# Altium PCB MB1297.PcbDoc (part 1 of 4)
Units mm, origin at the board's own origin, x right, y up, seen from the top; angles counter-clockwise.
Board outline 90.1 x 62.11 mm, 4 copper layers (Top Layer, GND, POWER+GND, Bottom Layer), stack 0.778 mm thick; 235 components, 175 nets, 1727 pads, 1 vias.
Unrouted connection lines stored in the file: 1.
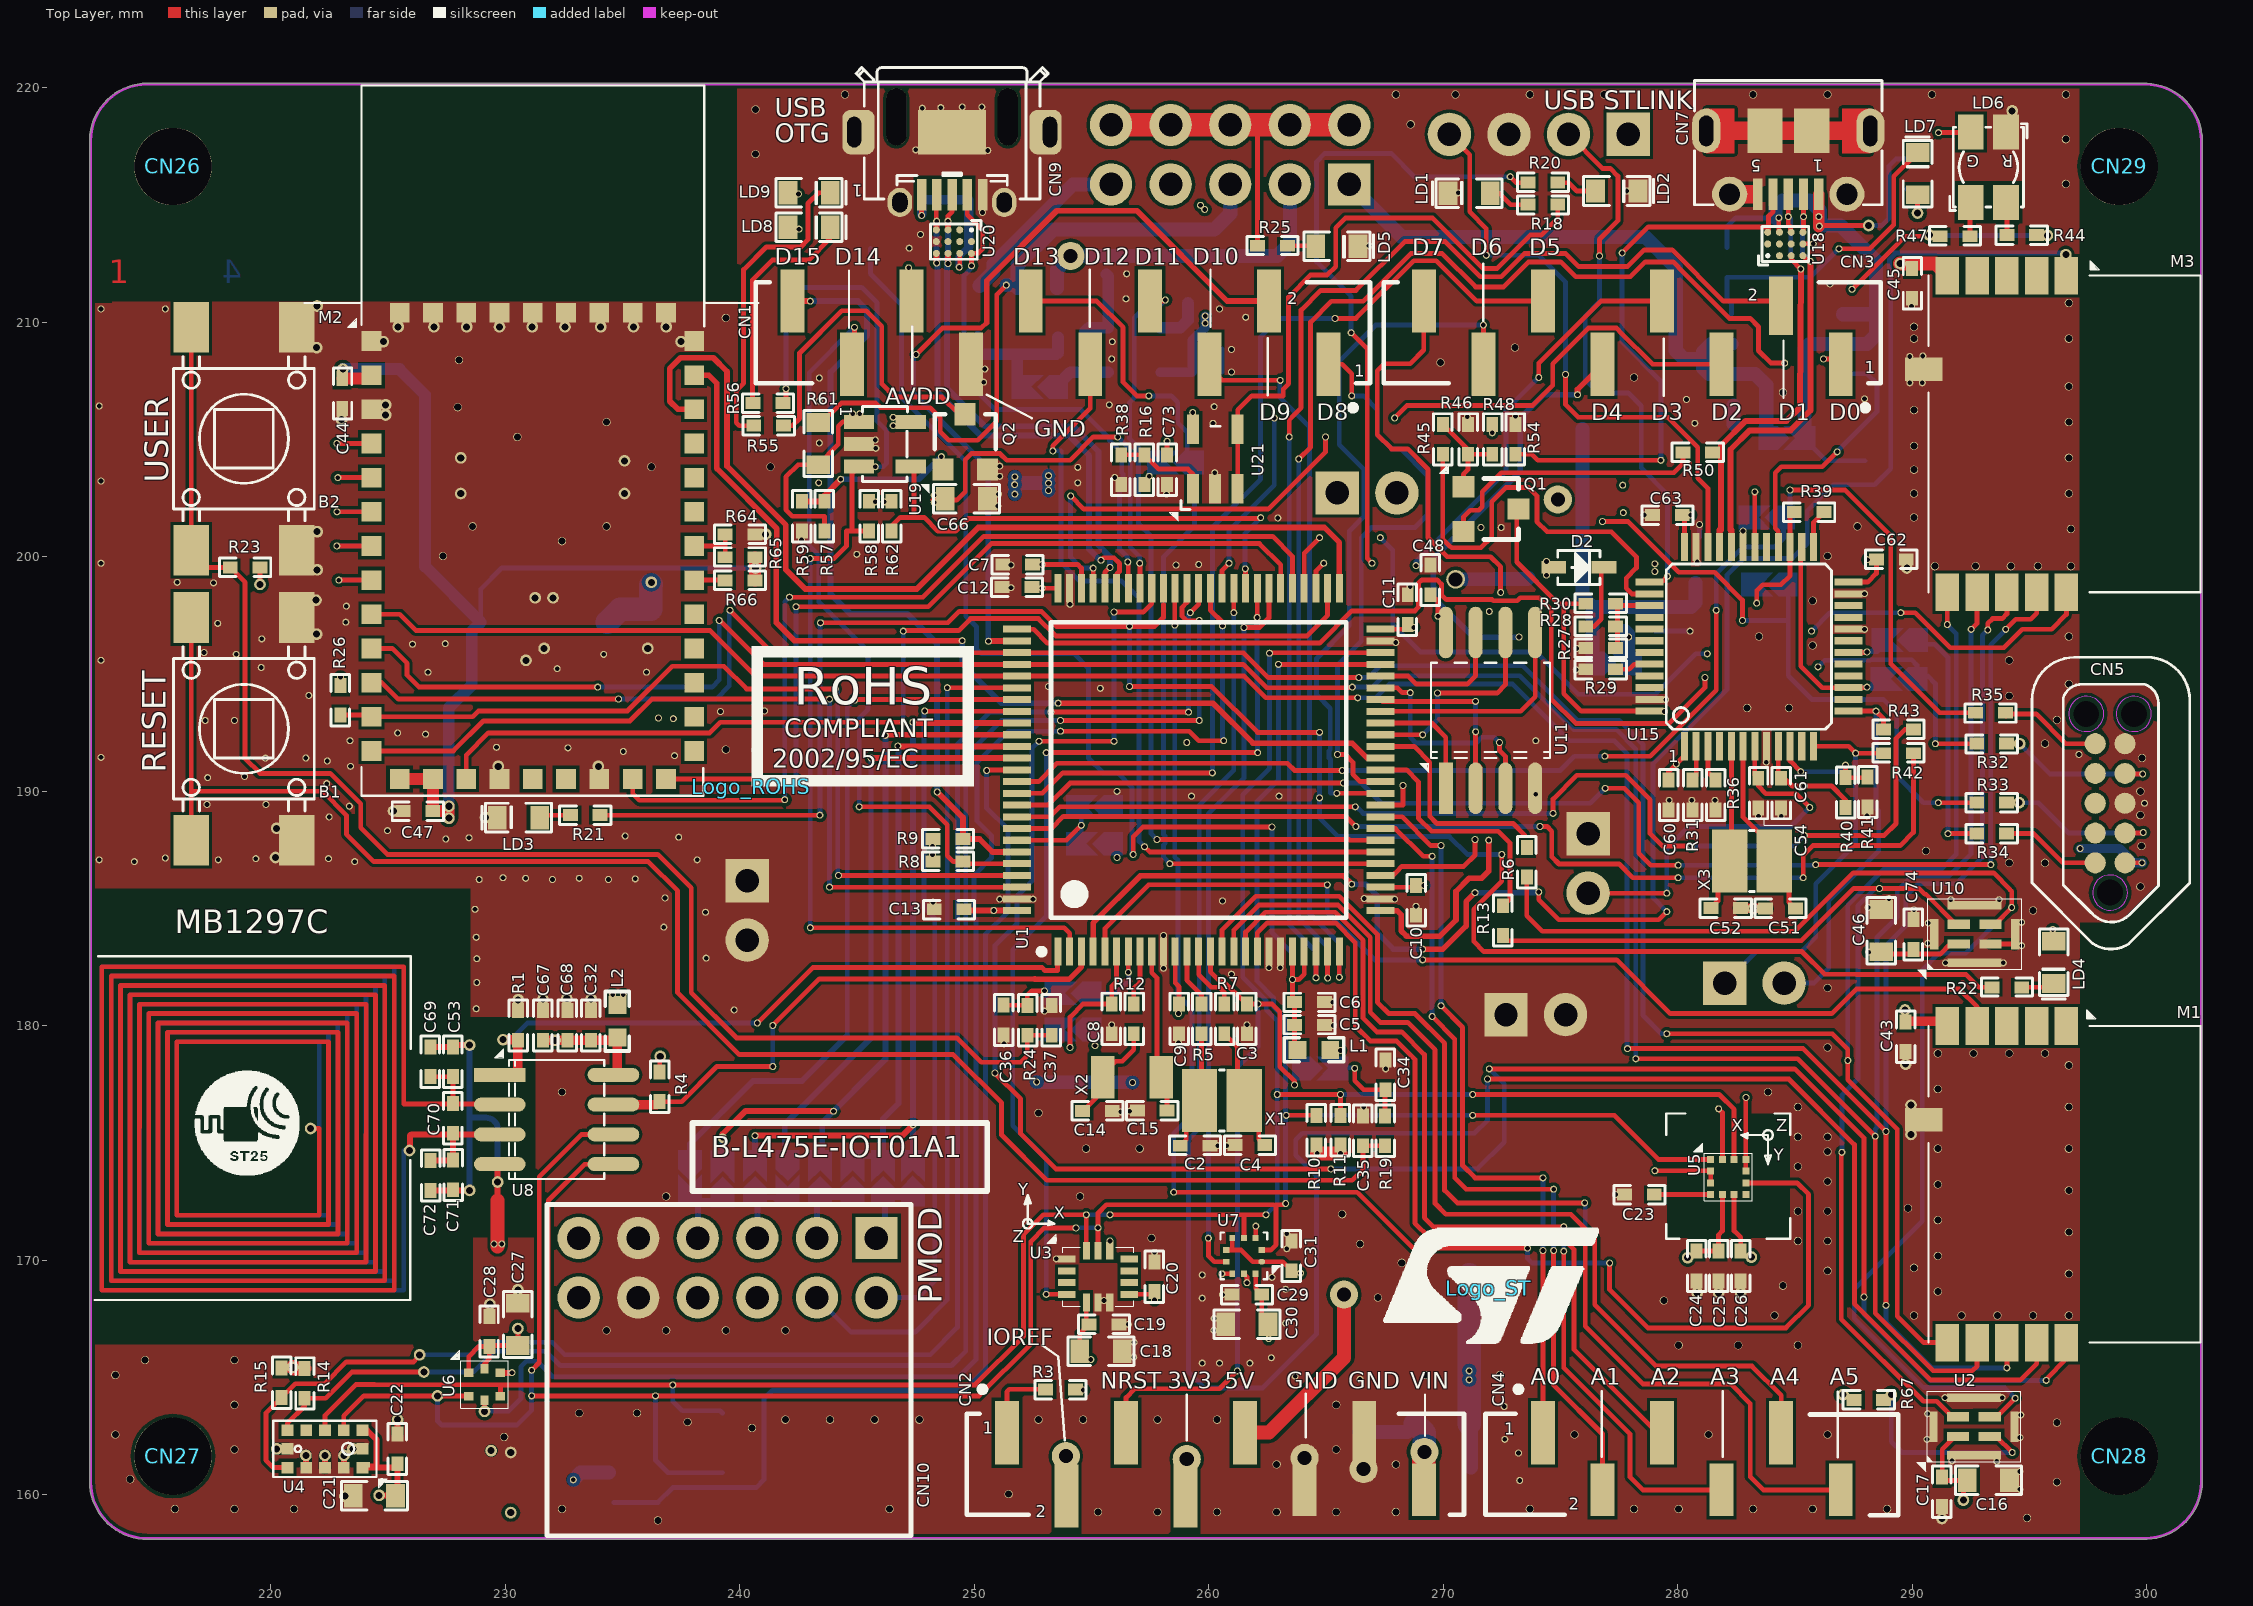
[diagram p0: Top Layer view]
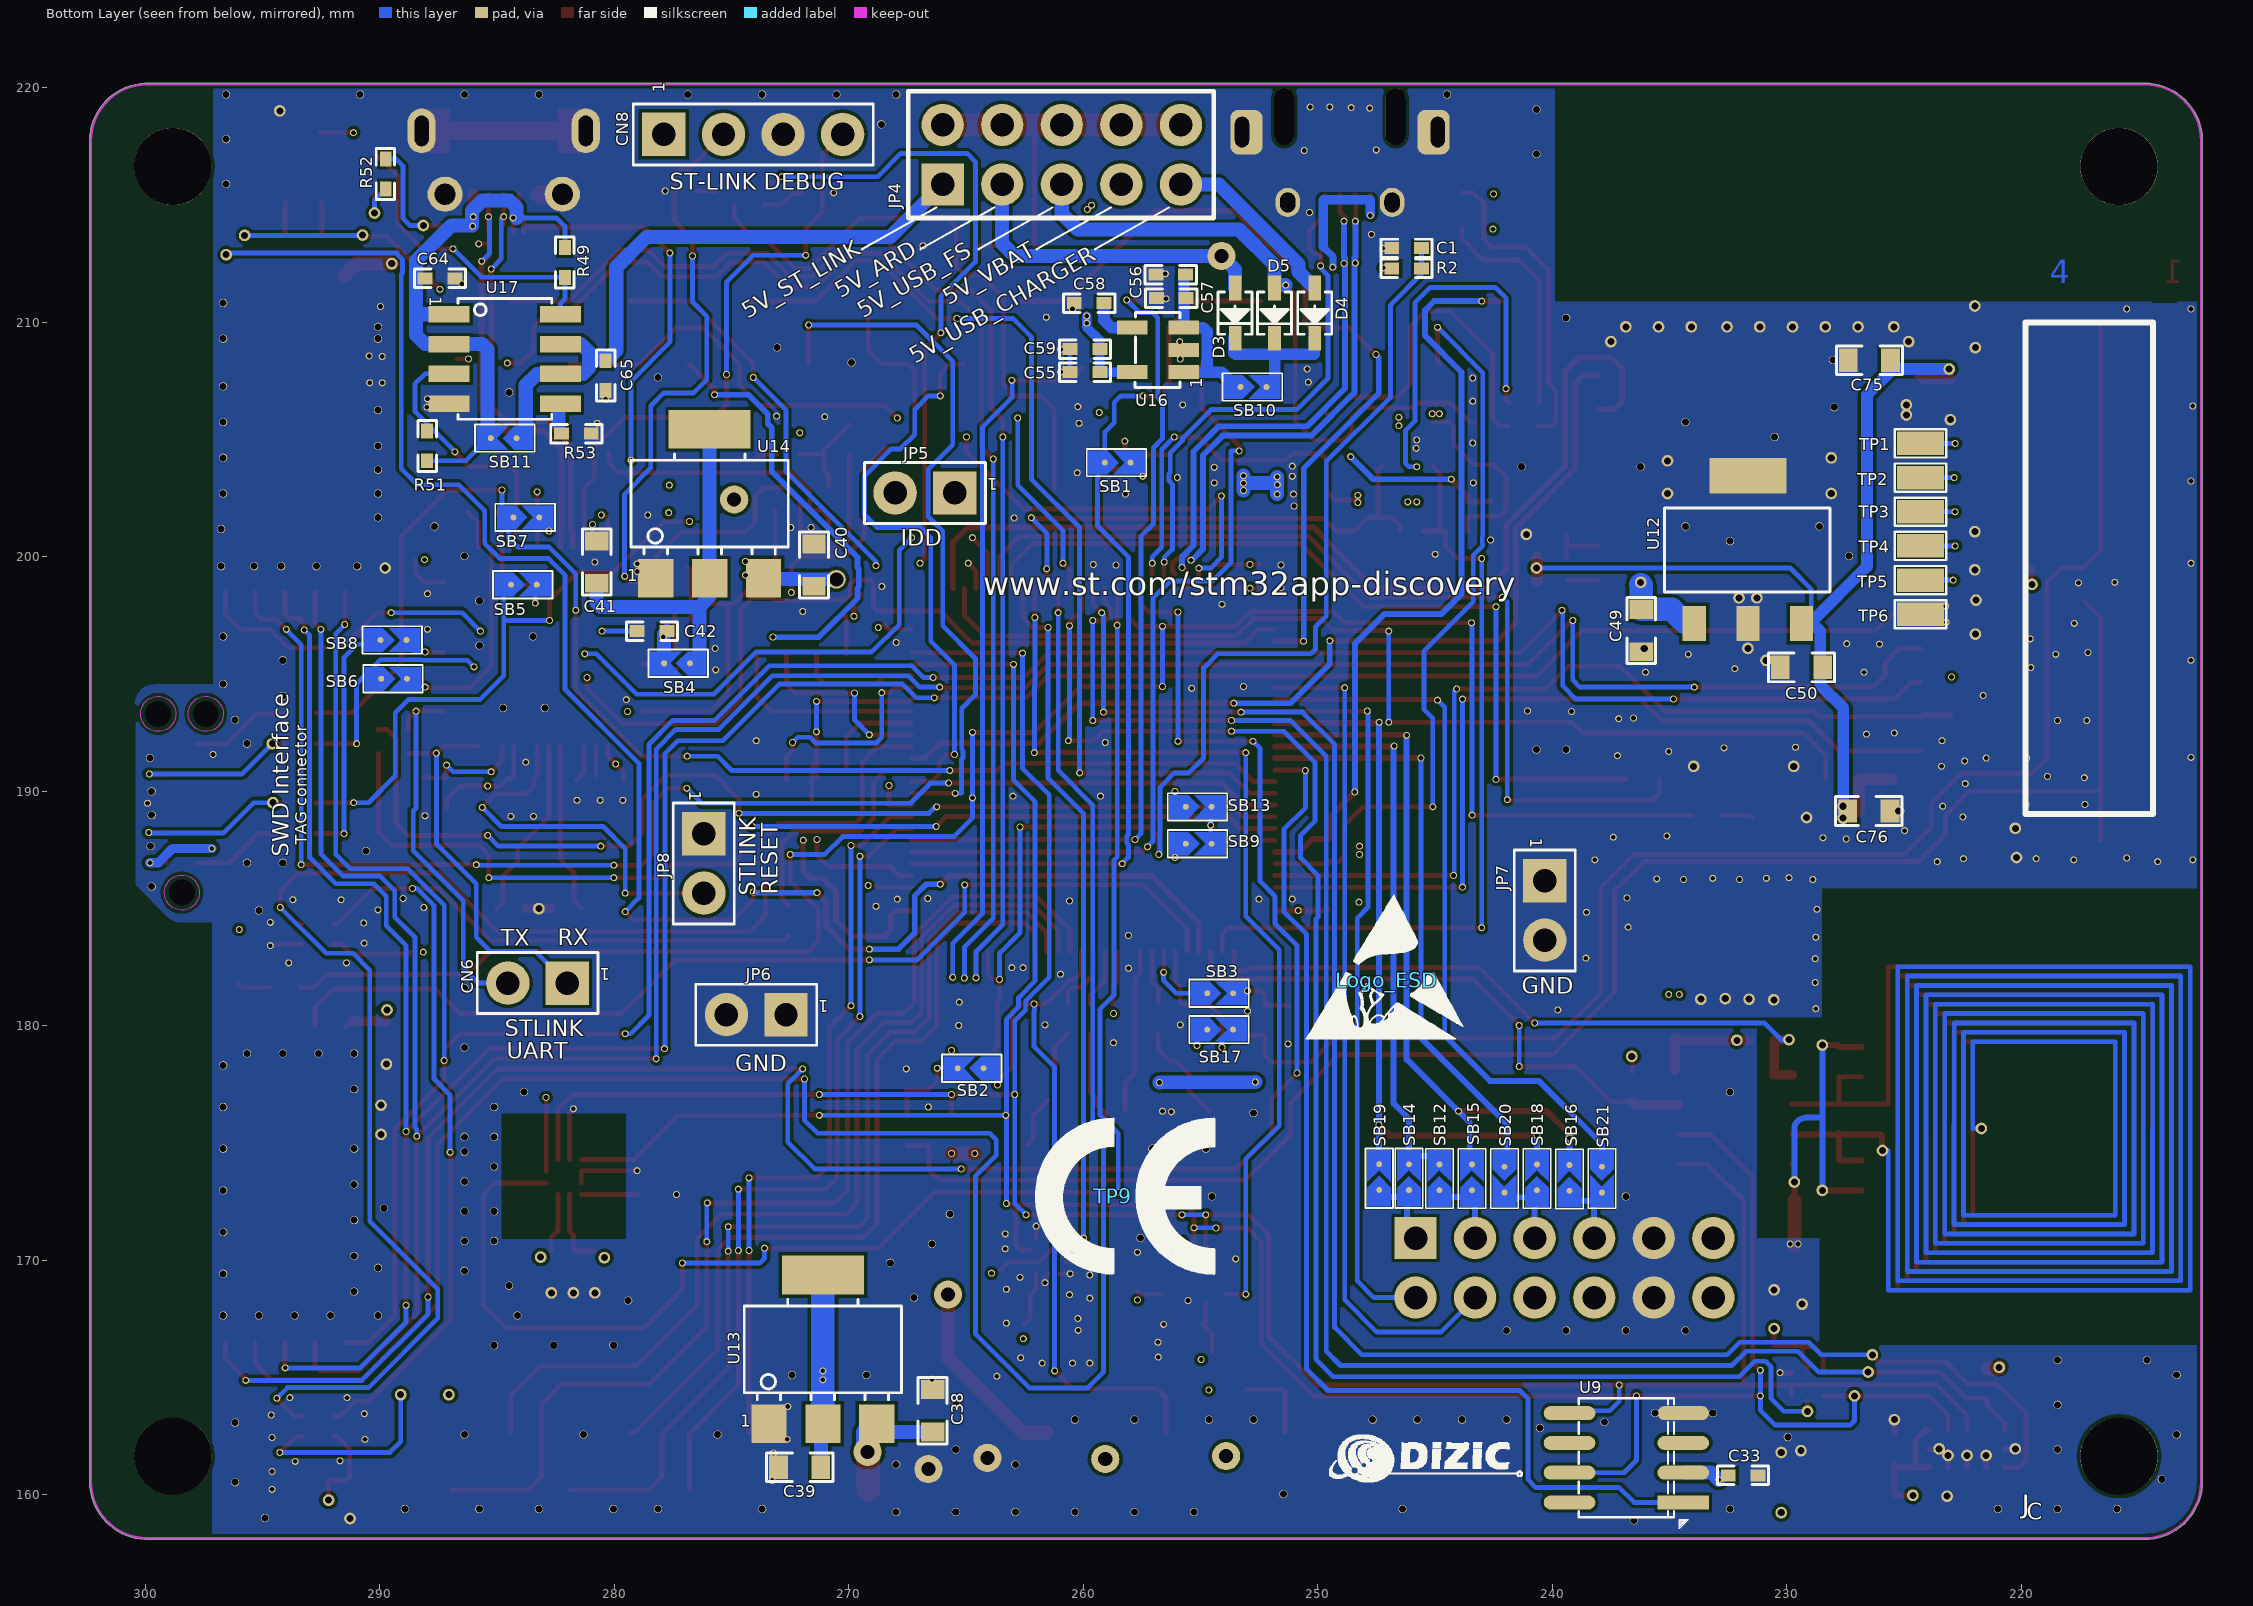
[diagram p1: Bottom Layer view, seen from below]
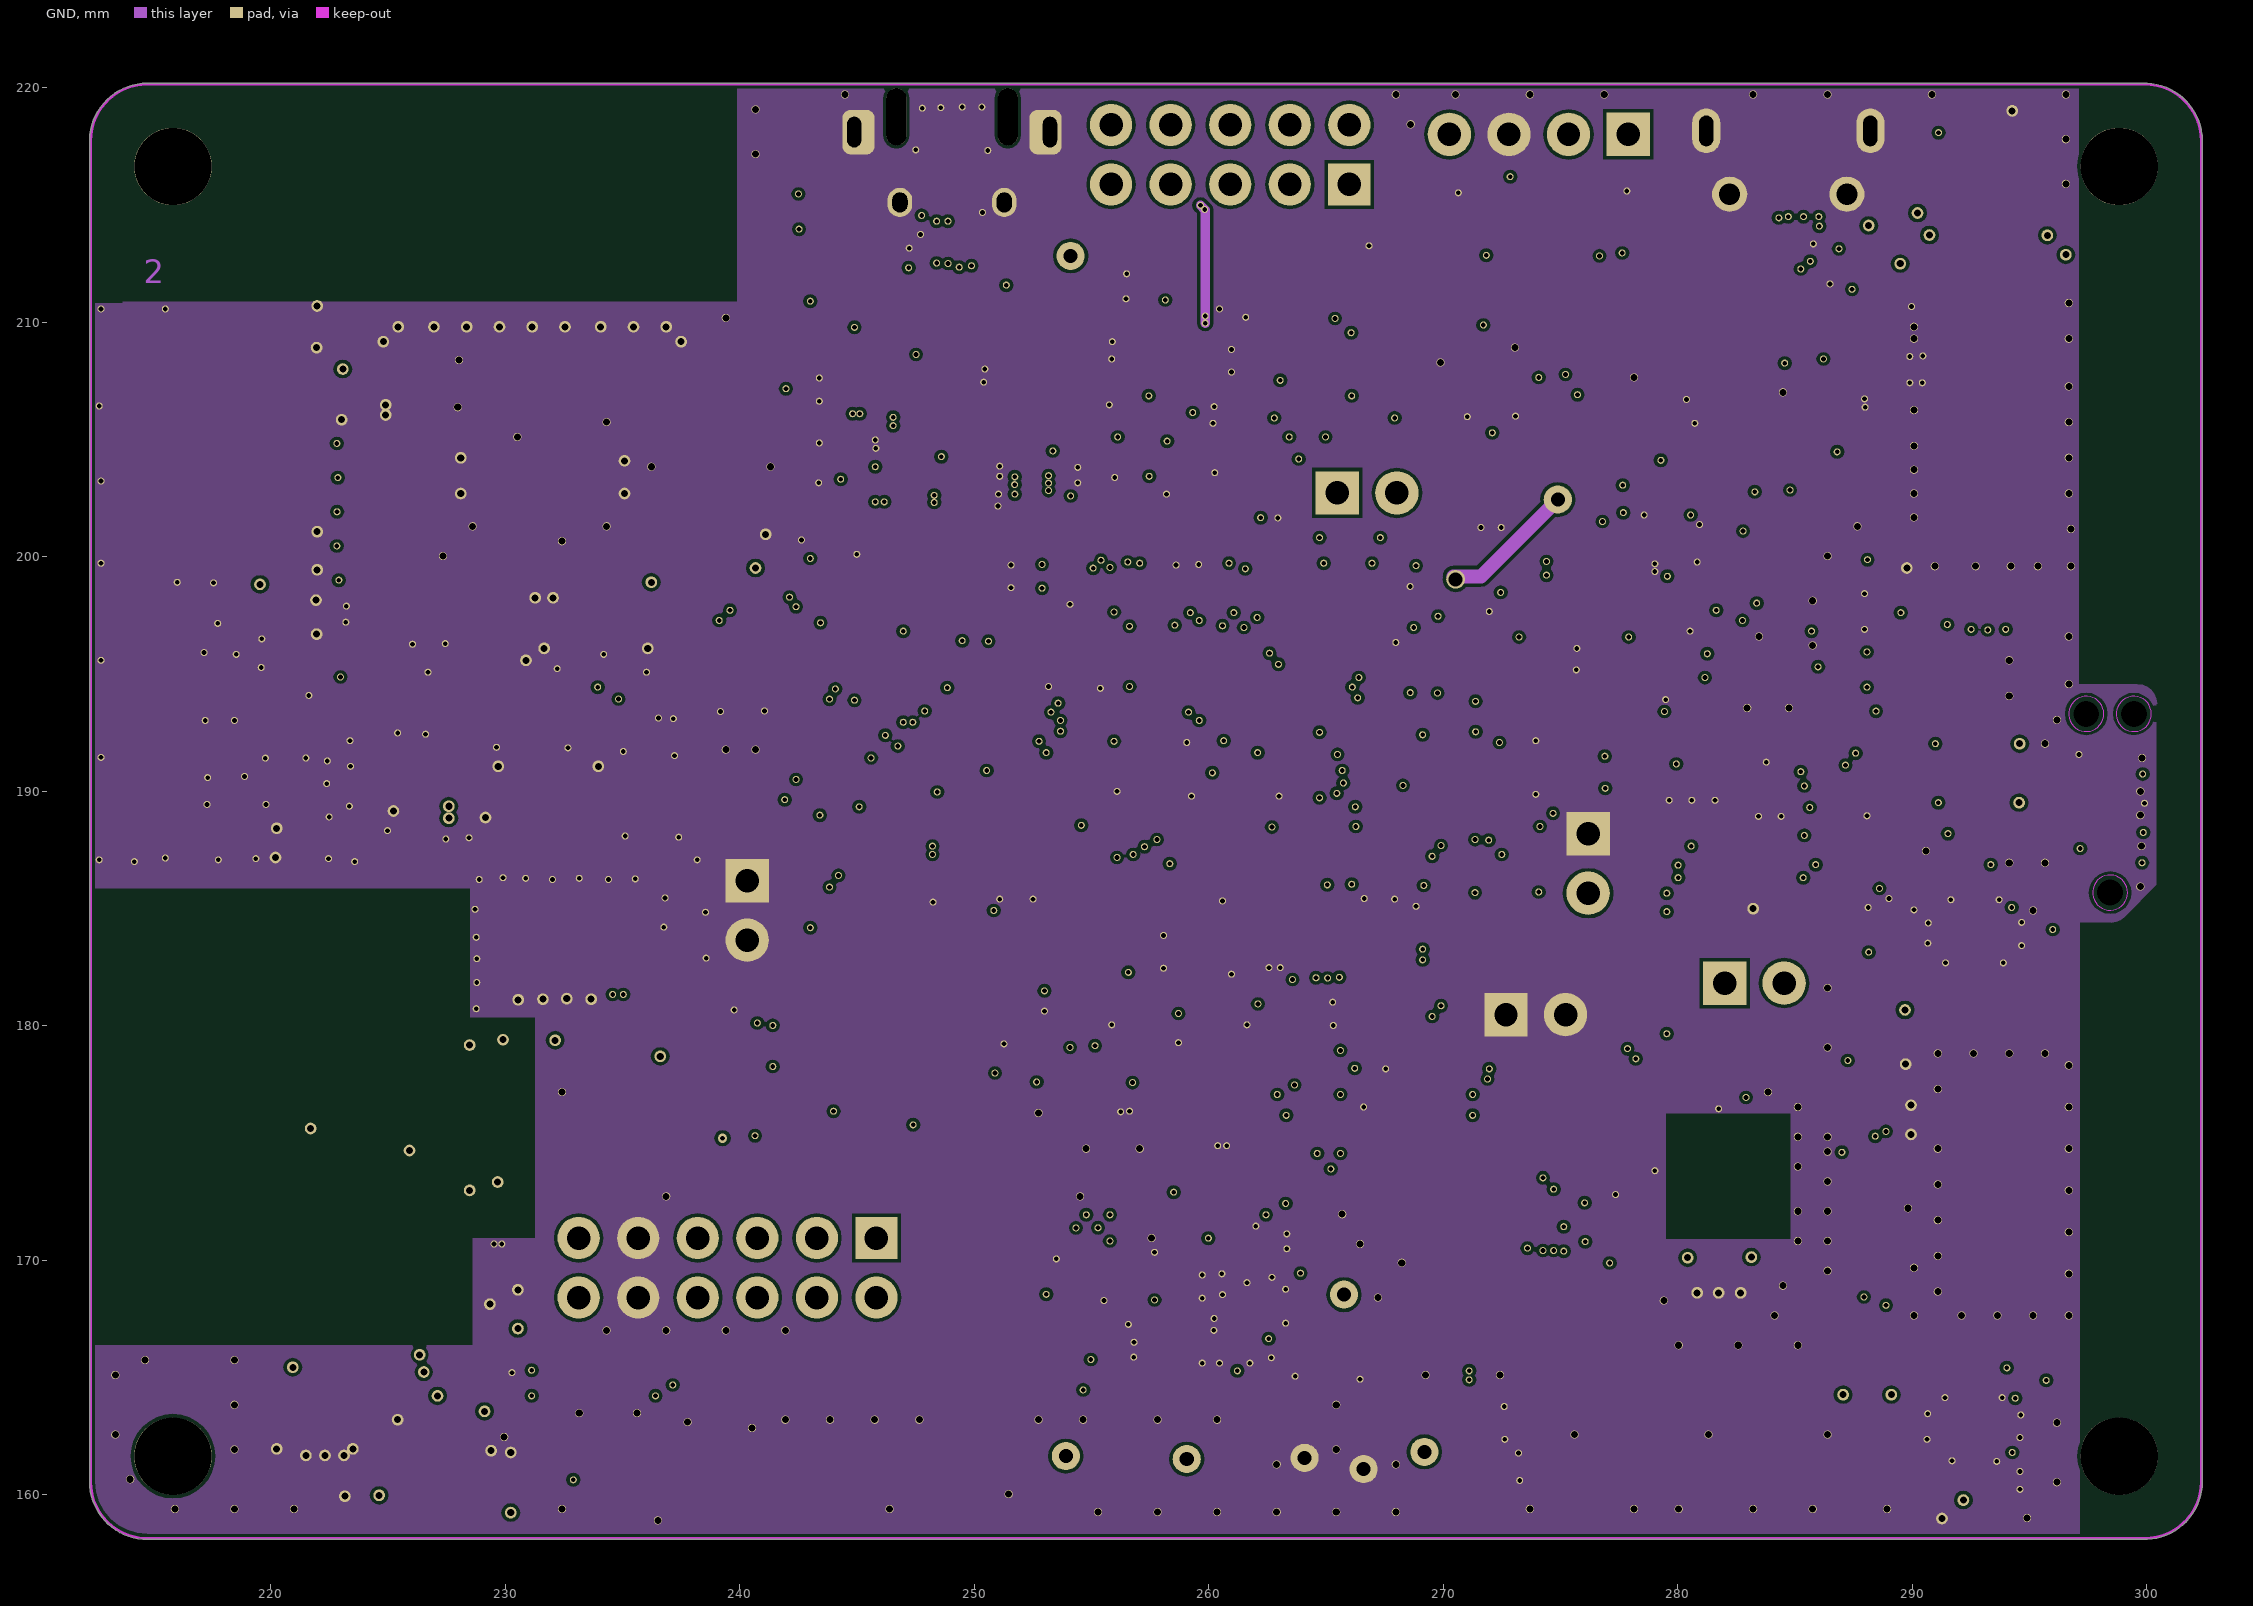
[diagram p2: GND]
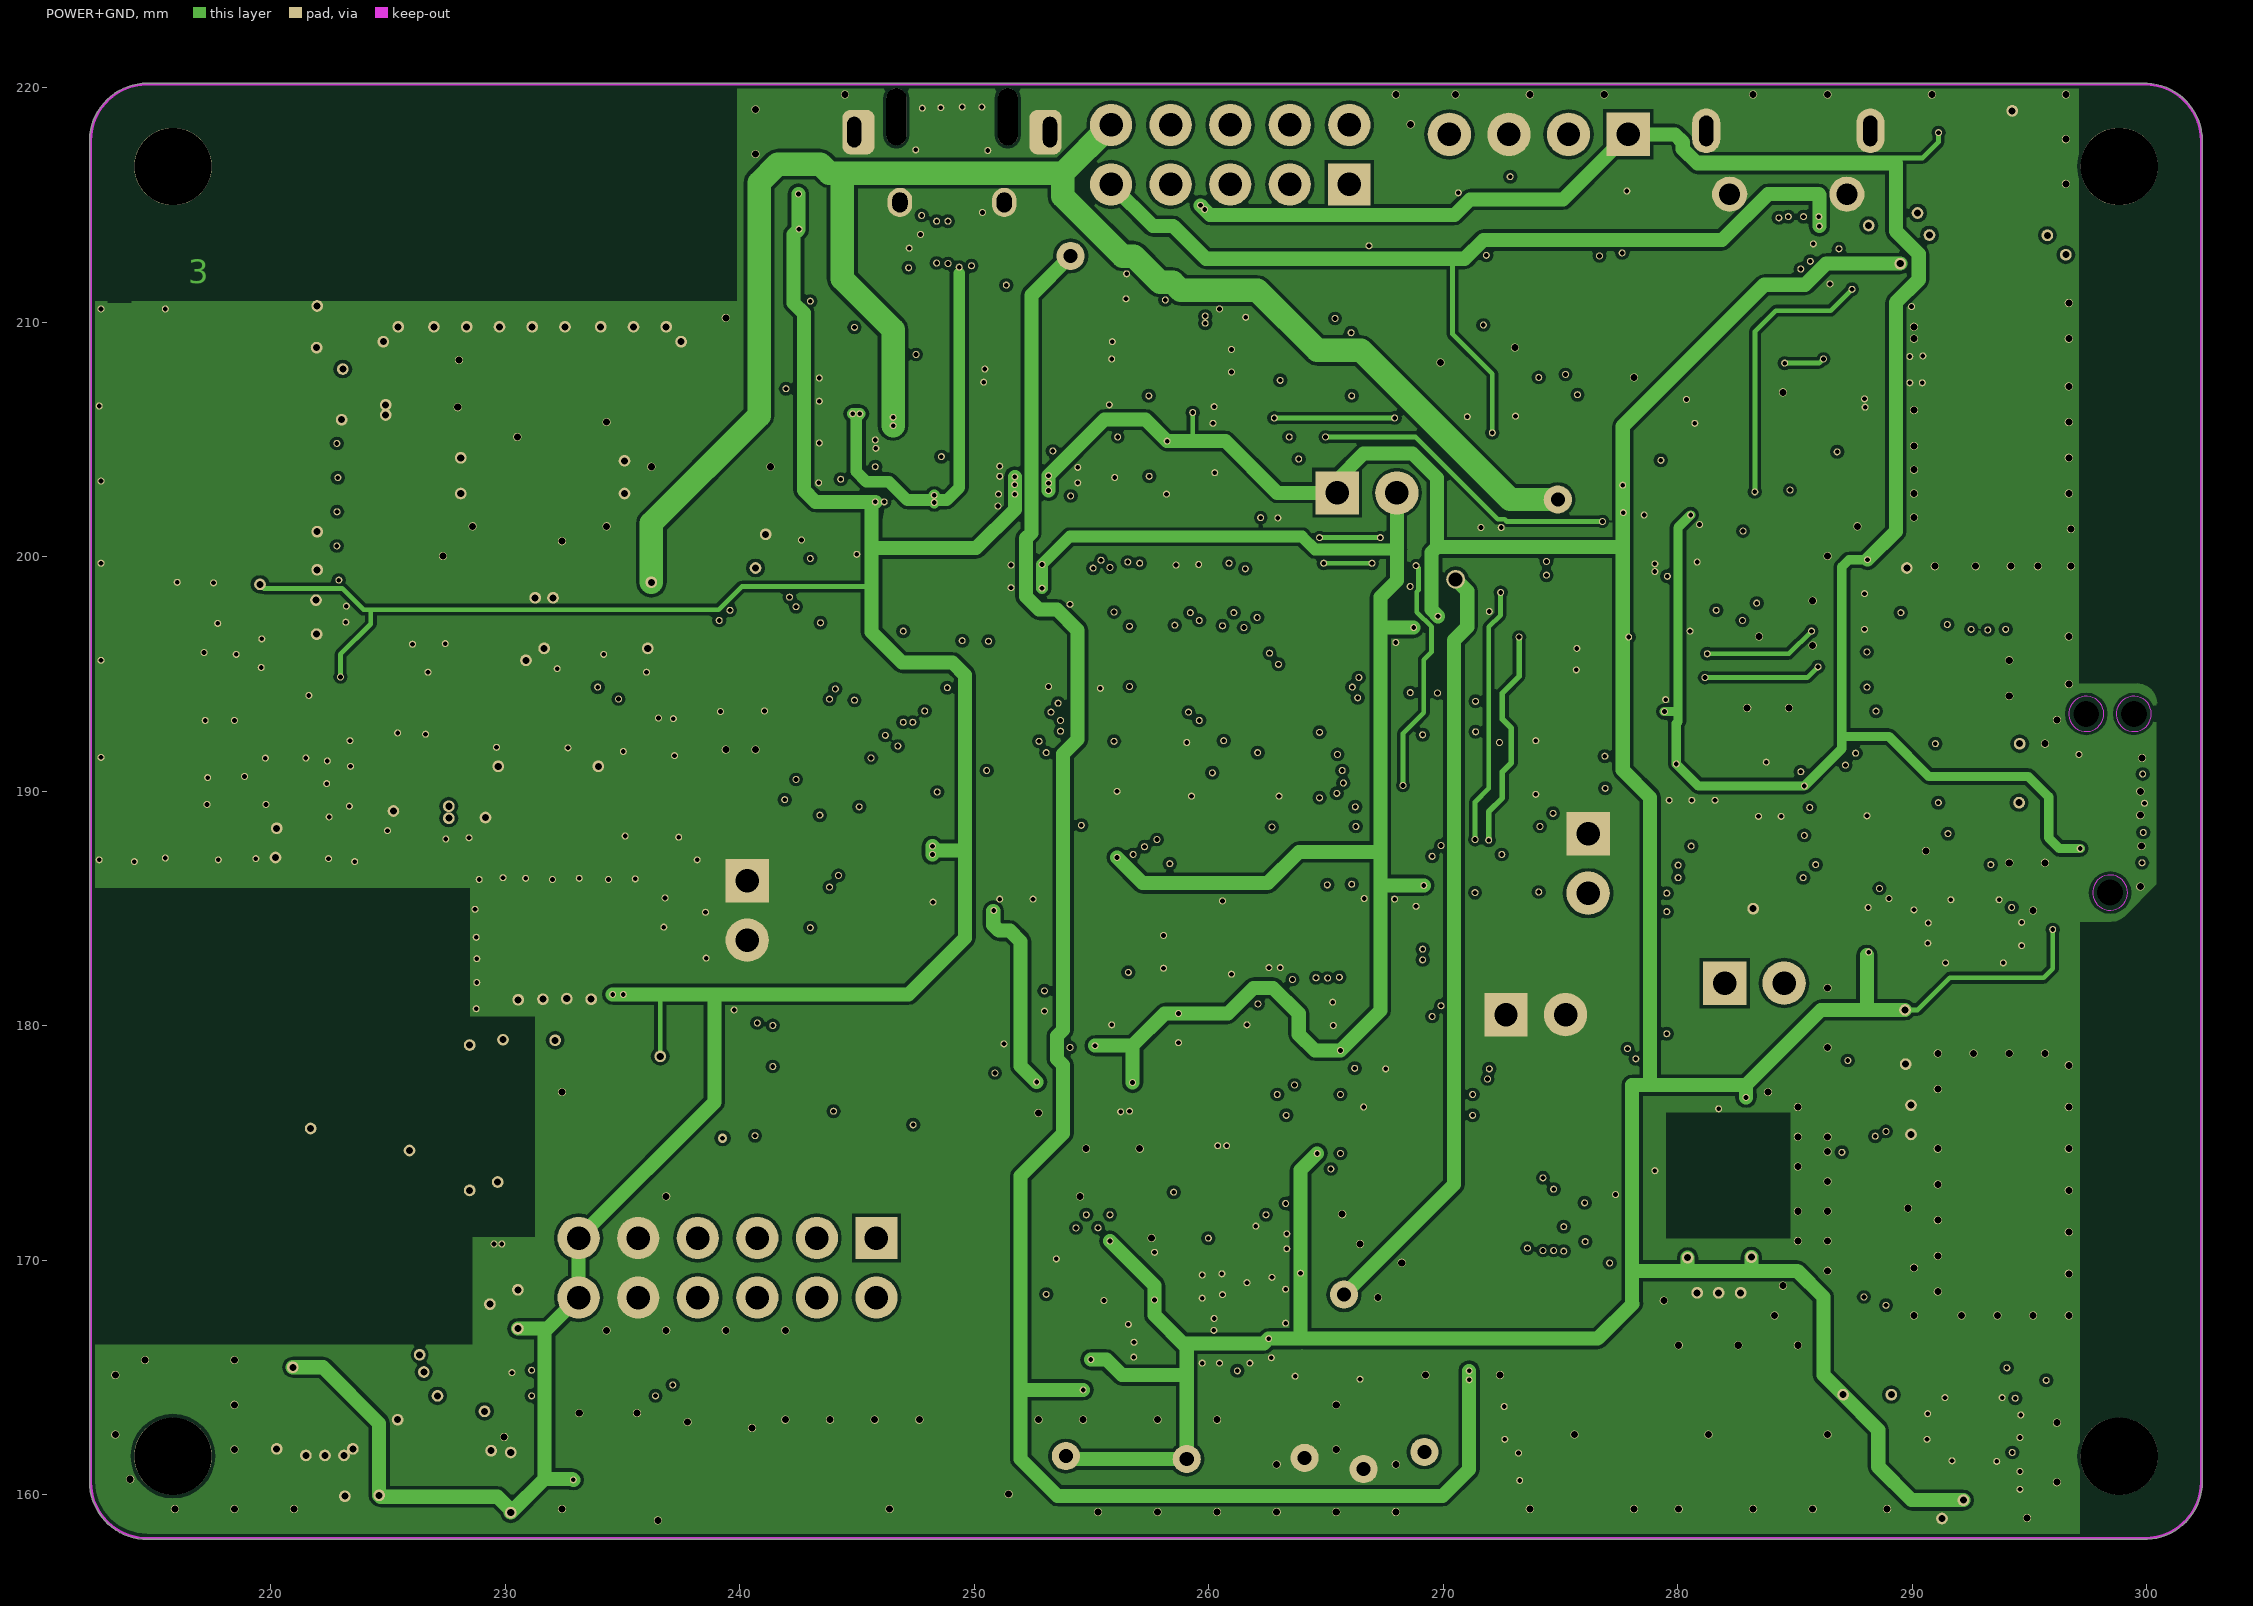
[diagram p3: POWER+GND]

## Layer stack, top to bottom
Top Layer: signal copper 0.0356
Dielectric: core 0.254, FR-4, Dk 4.2
GND: signal copper 0.036
Dielectric: prepreg 0.127, Dk 4.2
POWER+GND: signal copper 0.036
Dielectric: core 0.254, Dk 4.2
Bottom Layer: signal copper 0.0356

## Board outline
212.268,160.552 cw(c212.318,160.552) 212.268,160.559 212.268,217.707 cw(c212.315,217.727) 212.264,217.727 cw(c214.73,217.727) 212.268,217.865 212.268,217.955 cw(c212.319,217.955) 212.278,217.985 cw(c214.73,217.727) 214.73,220.193 cw(c214.73,220.142) 214.744,220.191 299.886,220.191 cw(c299.898,220.142) 299.898,220.192 cw(c299.898,217.726) 299.981,220.191 299.999,220.191 cw(c299.999,220.14) 300.01,220.19 cw(c299.898,217.726) 302.349,217.995 cw(c302.319,217.955) 302.369,217.955 302.369,160.555 cw(c302.319,160.555) 302.365,160.536 cw(c299.899,160.555) 300.016,158.092 cw(c300.001,158.14) 300.001,158.09 299.949,158.09 cw(c299.899,160.555) 299.899,158.09 cw(c299.899,158.14) 299.892,158.09 214.753,158.09 cw(c214.734,158.137) 214.734,158.086 cw(c214.734,160.552)

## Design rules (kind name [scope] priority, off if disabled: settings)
AssemblyTestPointUsage [All] p1 off:
AssemblyTestpoint [All] p1 off: testpointundercomponent=TRUE minsize=1.016 maxsize=2.54 preferedsize=1.524 minholesize=0 maxholesize=1.016 preferedholesize=0.813 testpointgrid=0.025 usegrid=TRUE gridtolerance=0 allowsidetop=TRUE allowsidebottom=TRUE
Clearance Clearance_Poly [InPolygon] p1: gap=0.14
Clearance [All] p2: gap=0.102
ComponentClearance [All] p1 off: gap=0.254 collisioncheckmode=3 verticalgap=0.254 showdistances=FALSE
DiffPairsRouting [All] p1: maxlimit=0.508 minlimit=0.145 mostfreqgap=0.145 maxuncoupledlength=12.7
FabricationTestPointUsage [All] p1 off: valid=0 allowmultiple=FALSE
FabricationTestpoint [All] p1 off: side=3 testpointundercomponent=TRUE minsize=1.016 maxsize=2.54 preferedsize=1.524 minholesize=0 maxholesize=1.016 preferedholesize=0.813 testpointgrid=0.025 allowsidetop=TRUE allowsidebottom=TRUE usegrid=TRUE gridtolerance=0
FanoutControl Fanout_BGA [IsBGA] p1 off: bgadir=Out bgaviamode=Centered fanoutstyle=Auto fanoutdirection=Alternating viagrid=0.025 // Fanout_BGA (Default Rule)
FanoutControl Fanout_LCC [IsLCC] p2 off: bgadir=Out bgaviamode=Centered fanoutstyle=Auto fanoutdirection=Alternating viagrid=0.025 // Fanout_LCC (Default Rule)
FanoutControl Fanout_SOIC [IsSOIC] p3 off: bgadir=Out bgaviamode=Centered fanoutstyle=Auto fanoutdirection=Alternating viagrid=0.025 // Fanout_SOIC (Default Rule)
FanoutControl Fanout_Small [(CompPinCount < 5)] p4 off: bgadir=Out bgaviamode=Centered fanoutstyle=Auto fanoutdirection=OutThenIn viagrid=0.025 // Fanout_Small (Default Rule)
FanoutControl Fanout_Default [All] p5 off: bgadir=Out bgaviamode=Centered fanoutstyle=Auto fanoutdirection=Alternating viagrid=0.025 // Fanout_Default (Default Rule)
Height [All] p1 off: minheight=0 maxheight=25.4 prefheight=12.7
HoleSize [All] p1: absolutevalues=TRUE maxlimit=3.3 minlimit=0.2 maxpercent=80.000 minpercent=20.000
HoleToHoleClearance [All] p1 off: gap=0.254 allowstackedmicrovias=TRUE
LayerPairs [All] p1 off: enforce=TRUE
MinimumSolderMaskSliver [All] p1 off: minsoldermaskwidth=0.254
NetAntennae [All] p1 off: netantennaetolerance=0
PasteMaskExpansion [All] p1 off: expansion=0
PolygonConnect [All] p1: connectstyle=Direct reliefconductorwidth=0.254 reliefentries=4 polygonreliefangle="90 Angle" airgapwidth=0.254
RoutingCorners [All] p1 off: cornerstyle=45-Degree minsetback=2.54 maxsetback=2.54
RoutingLayers [All] p1 off: top layer_v5=TRUE mid layer 1_v5=TRUE mid layer 2_v5=TRUE bottom layer_v5=TRUE
RoutingPriority [All] p1 off: routingpriority=0
RoutingTopology [All] p1 off: topology=Shortest
RoutingVias [All] p1: holewidth=0.2 width=0.3 viastyle="Through Hole" minholewidth=0.2 minwidth=0.4 maxholewidth=3.3 maxwidth=3
SilkToSilkClearance [All] p1 off: silktosilkclearance=0.254
SilkToSolderMaskClearance SilkscreenOverComponentPads [IsPad] p1 off: minsilkscreentomaskgap=0.254 clearancetoexposedcopper=TRUE
SolderMaskExpansion [All] p1 off: expansion=0.102
Width [All] p1: maxlimit=6 minlimit=0.102 preferedwidth=0.2
4 further rules are at their usual default settings.

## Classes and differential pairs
component class "USB_OTG_FS  Page 4/11": C66 CN9 IC19 IC20 LD8 LD9 Q2 R55 R56 R57 R58 R59 R61 R62 U19 U20
component class "STLink V2.1 Page 11/11": C51 C52 C54 C55 C56 C57 C58 C59 C60 C61 C62 C63 C64 C65 CN5 CN6 CN7 CN8 D2 D3 D4 D5 IC15 IC16 IC17 IC18 JP8 LD6 LD7 Q1 R27 R28 R29 R30 R31 R32 R33 R34 R35 R36 R37 R39 R40 R41 R42 R43 R44 R45 R46 R47 R48 R49 R50 R51 R52 R53 R54 SB5 SB6 SB7 SB8 SB10 SB11 U15 U16 U17 U18 X3
component class "RF Modules Page 5/11": C43 C44 C45 C47 C48 C49 C50 C75 C76 IC11 M1 M2 M3 R26 R64 R65 R66 TP1 TP2 TP3 TP4 TP5 TP6 U11 U12
component class "Power part Page 8/11": C38 C39 C40 C41 C42 HW1 HW2 HW3 HW4 IC13 IC14 JP4 JP5 JP6 JP7 LD5 R25 SB4 U13 U14
component class "Peripherals Page 10/11": B1 B2 C34 C35 C36 C37 C73 CN10 IC21 LD1 LD2 LD3 LD4 R16 R17 R18 R19 R20 R21 R22 R23 R24 R38 SB1 SB2 SB3 SB12 SB14 SB15 SB16 SB18 SB19 SB20 SB21 U21
component class "NFC & ST-SAFE  Page 7/11": C32 C33 C53 C67 C68 C69 C70 C71 C72 IC8 IC9 L2 R1 R4 U8 U9
component class "MEMS Part Page 6/11": C16 C17 C18 C19 C20 C21 C22 C23 C24 C25 C26 C27 C28 C29 C30 C31 C46 C74 IC2 IC3 IC4 IC5 IC6 IC7 R6 R13 R14 R15 R67 U2 U3 U4 U5 U6 U7 U10
component class "MCU2 Page 3/11": C2 C3 C4 C5 C6 C7 C8 C9 C10 C11 C12 C13 L1 R5 R6 R7 SB9 SB13 SB17 X1
component class "MCU1 Page 2/11": C14 C15 IC1 R8 R9 R10 R11 R12 R13 U1 X2
component class "Arduino Connectors Page 9/11": C1 CN1 CN2 CN3 CN4 R2 R3
differential pair USB: +USB_P -USB_N
differential pair USB_STLK: +USB_STLK_P -USB_STLK_N

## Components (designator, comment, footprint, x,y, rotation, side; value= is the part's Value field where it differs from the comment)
B1 "SW-PUSH-CMS_BLACK" "SWI_WEALTHMETAL_TD-0341_4P - BACK" 218.846,192.659 r0 top
B2 "SW-PUSH-CMS_BLUE" "SWI_WEALTHMETAL_TD-0341_4P - BLUE" 218.846,205.029 r0 top
C1 "100nF" 0402_CAP_NPOL 246.202,213.157 r0 bottom
C2 "Not Fitted (8.2pF)" 0402_CAP_NPOL 259.41,174.879 r0 top
C3 "100nF" 0402_CAP_NPOL 261.62,180.289 r90 top
C4 "Not Fitted (8.2pF)" 0402_CAP_NPOL 261.747,174.904 r180 top
C5 "100nF" 0402_CAP_NPOL 264.287,180.035 r0 top
C6 "1uF" 0402_CAP_NPOL 264.287,181 r180 top
C7 "100nF" 0402_CAP_NPOL 251.841,199.669 r180 top
C8 "1uF" 0402_CAP_NPOL 255.854,180.289 r90 top
C9 "100nF" 0402_CAP_NPOL 258.724,180.289 r270 top
C10 "100nF" 0402_CAP_NPOL 268.834,185.344 r270 top
C11 "100nF" 0402_CAP_NPOL 268.478,197.739 r90 top
C12 "100nF" 0402_CAP_NPOL 251.816,198.704 r180 top
C13 "100nF" 0402_CAP_NPOL 248.92,184.963 r180 top
C14 "5.1pF" 0402_CAP_NPOL 255.245,176.352 r0 top
C15 "5.1pF" 0402_CAP_NPOL 257.581,176.378 r180 top
C16 "10uF" 0603_CAP_NPOL 293.243,160.604 r0 top
C17 "100nF" 0402_CAP_NPOL 291.262,160.122 r90 top
C18 "4.7uF" 0603_CAP_NPOL 255.397,166.116 r0 top
C19 "100nF" 0402_CAP_NPOL 255.524,167.259 r0 top
C20 "100nF" 0402_CAP_NPOL 257.683,169.291 r90 top
C21 "4.7uF" 0603_CAP_NPOL 224.409,159.944 r180 top
C22 "100nF" 0402_CAP_NPOL 225.4,161.95 r90 top
C23 "100nF" 0402_CAP_NPOL 278.359,172.796 r180 top
C24 "1uF" 0402_CAP_NPOL 280.797,169.748 r270 top
C25 "100nF" 0402_CAP_NPOL 281.737,169.748 r270 top
C26 "100nF" 0402_CAP_NPOL 282.677,169.748 r270 top
C27 "2.2uF" 0603_CAP_NPOL 230.53,167.259 r90 top
C28 "100nF" 0402_CAP_NPOL 229.311,166.954 r90 top
C29 "100nF" 0402_CAP_NPOL 261.62,168.529 r180 top
C30 "4.7uF" 0603_CAP_NPOL 261.62,167.259 r180 top
C31 "100nF" 0402_CAP_NPOL 263.525,170.18 r90 top
C32 "100nF" 0402_CAP_NPOL 233.655,180.01 r90 top
C33 "100nF" 0402_CAP_NPOL 231.851,160.807 r180 bottom
C34 "100nF" 0402_CAP_NPOL 267.538,177.902 r90 top
C35 "10pF" 0402_CAP_NPOL 266.573,175.514 r90 top
C36 "100nF" 0402_CAP_NPOL 251.231,180.238 r270 top
C37 "10pF" 0402_CAP_NPOL 253.298,180.227 r90 top
C38 "10uF" 0603_CAP_NPOL 266.421,163.576 r90 bottom
C39 "10uF" 0603_CAP_NPOL 272.085,161.163 r0 bottom
C40 "10uF" 0603_CAP_NPOL 271.475,199.644 r90 bottom
C41 "10uF" 0603_CAP_NPOL 280.746,199.771 r90 bottom
C42 "100nF" 0402_CAP_NPOL 278.384,196.825 r0 bottom
C43 "100nF" 0402_CAP_NPOL 289.712,179.527 r270 top
C44 "100nF" 0402_CAP_NPOL 223.037,206.959 r270 top
C45 "100nF" 0402_CAP_NPOL 289.992,211.658 r270 top
C46 "10uF" 0603_CAP_NPOL 288.671,184.048 r90 top
C47 "100nF" 0402_CAP_NPOL 226.263,189.154 r180 top
C48 "100nF" 0402_CAP_NPOL 269.443,199.009 r90 top
C49 "10uF" 0603_CAP_NPOL 236.195,196.85 r270 bottom
C50 "10uF" 0603_CAP_NPOL 229.362,195.275 r0 bottom
C51 "10pF" 0402_CAP_NPOL 284.378,184.988 r0 top
C52 "10pF" 0402_CAP_NPOL 282.042,185.014 r180 top
C53 "47pF" 0402_CAP_NPOL 227.762,178.46 r90 top
C54 "100nF" 0402_CAP_NPOL 283.426,189.916 r270 top
C55 "100nF" 0402_CAP_NPOL 259.918,207.874 r0 bottom
C56 "1uF" 0402_CAP_NPOL 256.261,212.039 r0 bottom
C57 "100nF" 0402_CAP_NPOL 256.239,211.026 r0 bottom
C58 "10nF" 0402_CAP_NPOL 259.74,210.82 r0 bottom
C59 "1uF" 0402_CAP_NPOL 259.918,208.864 r0 bottom
C60 "100nF" 0402_CAP_NPOL 279.603,189.84 r270 top
C61 "100nF" 0402_CAP_NPOL 284.391,189.916 r270 top
C62 "100nF" 0402_CAP_NPOL 289.103,199.873 r0 top
C63 "100nF" 0402_CAP_NPOL 279.552,201.778 r180 top
C64 "1uF" 0402_CAP_NPOL 287.426,211.861 r180 bottom
C65 "100nF" 0402_CAP_NPOL 280.365,207.721 r270 bottom
C66 "4.7uF" 0603_CAP_NPOL 249.657,202.463 r0 top
C67 "100pF" 0402_CAP_NPOL 231.597,180.01 r90 top
C68 "1uF" 0402_CAP_NPOL 232.639,180.01 r90 top
C69 "Not Fitted" 0402_CAP_NPOL 226.797,178.46 r90 top
C70 "Not Fitted" 0402_CAP_NPOL 227.762,176.047 r90 top
C71 "47pF" 0402_CAP_NPOL 227.762,173.634 r270 top
C72 "Not Fitted" 0402_CAP_NPOL 226.797,173.609 r270 top
C73 "100nF" 0402_CAP_NPOL 258.216,203.708 r270 top
C74 "100nF" 0402_CAP_NPOL 290.043,183.89 r90 top
C75 "2.2uF" 0603_CAP_NPOL 226.466,208.382 r0 bottom
C76 "2.2uF" 0603_CAP_NPOL 226.492,189.154 r180 bottom
CN1 "Header 10X1_Female_SMD" F-V50XC-1X10R-LF 253.671,209.552 r0 top locked
CN2 "Header 8X1_Female_SMD" F-V50XC-1X08R-LF#1 260.275,161.292 r180 top locked
CN3 "Header 8X1_Female_SMD" F-V50XC-1X08R-LF#2 278.055,209.552 r0 top locked
CN4 "Header 6X1_Female_SMD" F-V50XC-1X06R-LF 280.595,161.292 r180 top locked
CN5 "TC2050-IDC-NL" CON_TAG-C_TC2050-IDC-NL 298.433,189.484 r90 top
CN6 "header 2 pins 2.54mm" CON_SAMTEC_TSW-102-07-G-S 283.261,181.813 r0 bottom
CN7 "1050170001" CON_USBMICROB_MOLEX_105017-0001_H2P90 284.709,219.608 r180 top
CN8 "Header 4 pins" CON_SAMTEC_TSW-104-07-G-S 274.066,218.008 r180 bottom
CN9 "475900001" CON_USBMICROAB_MOLEX_47590-0001_H3 249.047,219.558 r180 top
CN10 "HEADER_2X6_PMOD" "Header F 2x6x2.54 TH H PMOD" 245.821,170.942 r180 top
CN26 "Comment" "Spacer+Nut M3" 215.819,216.64 r90 top
CN27 "Comment" "Spacer+Nut M3" 215.819,161.64 r90 top
CN28 "Comment" "Spacer+Nut M3" 298.819,161.64 r90 top
CN29 "Comment" "Spacer+Nut M3" 298.819,216.64 r90 top
D2 "BAT60JFILM" DIO_SOD323 275.775,199.542 r0 top
D3 "BAT60JFILM" DIO_SOD323 253.517,210.388 r270 bottom
D4 "BAT60JFILM" DIO_SOD323 250.121,210.387 r270 bottom
D5 "BAT60JFILM" DIO_SOD323 251.835,210.387 r270 bottom
JP4 "HEADER_2X5" "Header M 2x5x2.54 TH V" 265.989,215.875 r180 bottom
JP5 "Jumper_2.54mm" CON_SAMTEC_TSW-102-07-G-S 266.747,202.717 r0 bottom
JP6 "Jumper_2.54mm" CON_SAMTEC_TSW-102-07-G-S 273.939,180.467 r0 bottom
JP7 "Jumper_2.54mm" CON_SAMTEC_TSW-102-07-G-S 240.309,184.916 r270 bottom
JP8 "Jumper_2.54mm" CON_SAMTEC_TSW-102-07-G-S 276.174,186.919 r270 bottom
L1 "FCM1608KF-601T03" 0603L 264.477,178.968 r0 top
L2 "742792042" 0603L 234.772,180.188 r270 top
LD1 "LED" 0603_LED_GREEN 271.094,215.494 r0 top
LD2 "LED" 0603_LED_GREEN 277.393,215.595 r180 top
LD3 "LED" 0603_LED_Yellow 230.556,188.874 r0 top
LD4 "LED" 0603_LED_Blue 296.037,182.702 r90 top
LD5 "LED" 0603_LED_GREEN 265.455,213.233 r180 top
LD6 "LD_BICOLOR_CMS" LED_BI-GR_HSMF-A201-A00J1 293.243,216.611 r180 top
LD7 "LED" 0603_LED_RED 290.22,216.332 r270 top
LD8 "LED" 0603_LED_RED 242.951,214.046 r180 top
LD9 "LED" 0603_LED_GREEN 242.951,215.519 r180 top
Logo_ESD "Comment" SYMBOL_ESD 247.04,181.94 r180 bottom
Logo_ROHS "Comment" SYMBOL_RoHS 240.487,190.195 r0 top
Logo_ST "Comment" LOGO_ST_Size3 271.932,168.808 r0 top
M1 "BT Module" SPBTLE-RF 296.57,179.984 r270 top
M2 "ISM43362-M3G-L44" ISM43362-M3G-L44 231.165,200.457 r90 top locked
M3 "SPSGRF" SPSGRF 296.57,211.988 r270 top
Q1 "BSR14" SOT23-3 273.202,202.032 r270 top
Q2 "BSR14" SOT23-3 249.606,206.07 r0 top
R1 "30K" 0402_RES 230.53,180.01 r270 top
R2 "0R" 0402_RES 246.202,212.293 r180 bottom
R3 "1K" 0402_RES 253.67,164.49 r180 top
R4 "20K" 0402_RES 236.576,177.394 r270 top
R5 "Not Fitted (0R)" 0402_RES 259.69,180.289 r270 top
R6 "0R" 0402_RES 273.558,186.969 r90 top
R7 "Not Fitted (0R)" 0402_RES 260.655,180.289 r270 top
R8 "2K2" 0402_RES 248.869,186.995 r0 top
R9 "2K2" 0402_RES 248.869,187.96 r0 top
R10 "2K2" 0402_RES 264.592,175.539 r90 top
R11 "2K2" 0402_RES 265.608,175.539 r90 top
R12 "0R" 0402_RES 256.794,180.289 r270 top
R13 "0R" 0402_RES 272.542,184.48 r90 top
R14 "10K" 0402_RES 221.437,164.744 r270 top
R15 "10K" 0402_RES 220.447,164.77 r270 top
R16 "10K" 0402_RES 257.251,203.708 r90 top
R18 "1K" 0402_RES 274.244,215.011 r180 top
R19 "1K" 0402_RES 267.513,175.514 r270 top
R20 "330R" 0402_RES 274.244,215.951 r0 top
R21 "1K" 0402_RES 233.401,188.976 r180 top
R22 "680R" 0402_RES 294.03,181.635 r0 top
R23 "100K" 0402_RES 218.897,199.542 r0 top
R24 "1K" 0402_RES 252.256,180.227 r270 top
R25 "330R" 0402_RES 262.712,213.258 r0 top
R26 "47K" 0402_RES 222.961,193.878 r90 top
R27 "4K7" 0402_RES 276.708,196.113 r180 top
R28 "2K7" 0402_RES 276.708,197.028 r0 top
R29 "100K" 0402_RES 276.708,195.199 r180 top
R30 "Not Fitted (0R)" 0402_RES 276.708,197.993 r0 top
R31 "10K" 0402_RES 280.619,189.84 r270 top
R32 "22R" 0402_RES 293.383,192.024 r180 top
R33 "22R" 0402_RES 293.383,189.509 r180 top
R34 "22R" 0402_RES 293.383,188.189 r180 top
R35 "22R" 0402_RES 293.332,193.345 r180 top
R36 "Not Fitted (10K)" 0402_RES 281.61,189.84 r270 top
R38 "200K" 0402_RES 256.261,203.708 r90 top
R39 "100R" 0402_RES 285.598,201.905 r180 top
R40 "4K7" 0402_RES 287.147,189.941 r270 top
R41 "4K7" 0402_RES 288.087,189.967 r270 top
R42 "0R" 0402_RES 289.408,191.618 r0 top
R43 "0R" 0402_RES 289.408,192.634 r0 top
R44 "330R" 0402_RES 294.665,213.716 r180 top
R45 "100R" 0402_RES 269.977,205.003 r90 top
R46 "36K" 0402_RES 271.043,205.003 r270 top
R47 "330R" 0402_RES 291.821,213.665 r0 top
R48 "10K" 0402_RES 272.085,205.003 r270 top
R49 "100K" 0402_RES 282.092,212.547 r90 bottom
R50 "1K5" 0402_RES 280.848,204.445 r0 top
R51 "10K" 0402_RES 287.985,204.724 r270 bottom
R52 "1K" 0402_RES 289.738,216.319 r90 bottom
R53 "2K2" 0402_RES 281.61,205.257 r0 bottom
R54 "100K" 0402_RES 273.075,205.003 r90 top
R55 "330R" 0402_RES 241.224,205.588 r180 top
R56 "1K" 0402_RES 241.198,206.553 r180 top
R57 "47K" 0402_RES 243.606,201.727 r90 top
R58 "47K" 0402_RES 245.501,201.727 r270 top
R59 "100K" 0402_RES 242.646,201.727 r90 top
R61 "0R" 0603_RES 243.332,204.826 r270 top
R62 "47K" 0402_RES 246.461,201.727 r270 top
R64 "Not Fitted (10K)" 0402_RES 240.005,200.939 r0 top
R65 "Not Fitted (10K)" 0402_RES 240.005,199.974 r0 top
R66 "Not Fitted (10K)" 0402_RES 240.005,198.984 r0 top
R67 "10K" 0402_RES 288.138,164.033 r0 top
SB1 "Close" SB 258.572,204.013 r180 bottom
SB2 "Close" SB 264.744,178.181 r0 bottom
SB3 "Close" SB 254.203,181.381 r180 bottom
SB4 "Close" SB 277.266,195.453 r0 bottom
SB5 "Close" SB 283.896,198.806 r180 bottom
SB6 "Close" SB 289.433,194.793 r180 bottom
SB7 "Close" SB 283.794,201.676 r180 bottom
SB8 "Close" SB 289.458,196.444 r180 bottom
SB9 "Open" SB 255.118,187.757 r180 bottom
SB10 "Close" SB 252.781,207.239 r180 bottom
SB11 "Open" SB 284.658,205.054 r0 bottom
SB12 "Open" SB 244.802,173.482 r90 bottom
SB13 "Close" SB 255.118,189.332 r180 bottom
SB14 "Close" SB 246.101,173.488 r90 bottom
SB15 "Close" SB 243.415,173.482 r90 bottom
SB16 "Open" SB 239.257,173.457 r90 bottom
SB17 "Close" SB 254.203,179.832 r180 bottom
SB18 "Close" SB 240.643,173.482 r90 bottom
SB19 "Open" SB 247.371,173.492 r90 bottom
SB20 "Open" SB 242.029,173.482 r270 bottom
SB21 "Close" SB 237.871,173.482 r270 bottom
TP1 "PT" PTB 224.291,204.828 r180 bottom
TP2 "PT" PTB 224.291,203.371 r180 bottom
TP3 "PT" PTB 224.291,201.914 r180 bottom
TP4 "PT" PTB 224.291,200.457 r180 bottom
TP5 "PT" PTB 224.291,199 r180 bottom
TP6 "PT" PTB 224.291,197.543 r180 bottom
TP9 "Comment" "LOGO CE" 258.732,172.729 r180 bottom
U1 "STM32L475VGTx" "LQFP100 14x14x1.6" 259.563,190.906 r90 top
U2 "MP34DT01-M" "HCLGA-4LD 3x4x1" 292.625,162.902 r90 top
U3 "LSM6DSL" LGA14L-2.5X3X0.86p0.5 255.27,169.291 r0 top
U4 "VL53L0X" LGA12-optical 222.301,161.95 r0 top
U5 "LIS3MDL" VFLGA12-2x2x1 282.147,173.545 r0 top
U6 "HTS221" HLGA6L-2x2x0.9 229.108,164.694 r0 top
U7 "LPS22HB" HLGA10L-2X2X0.76 261.493,170.18 r180 top
U8 "M24SR64-Y" SOP8 232.181,175.997 r0 top
U9 "STSAFE-A100" SOP8 236.83,161.569 r0 bottom
U10 "MP34DT01-M" "HCLGA-4LD 3x4x1" 292.659,183.906 r90 top
U11 "MX25R6435F" SOP8L 272.009,193.446 r90 top
U12 "LT1963EST-3.3" SOT223_SC73 231.648,200.304 r180 bottom
U13 "LD1117S50TR" REG_SOT223-TAB 271.098,166.192 r180 bottom
U14 "LD1117S33TR" REG_SOT223-TAB 275.924,202.26 r180 bottom
U15 "STM32F103CBT6" ICC_LQFP48_7X7_P050 283.032,196.164 r0 top
U16 "LD3985M33R" REG_SOT23-5L 256.812,208.817 r90 bottom
U17 "ST890CDR" ICC_SO8_5X4_P127 284.658,208.432 r270 bottom
U18 "EMIF02-USB03F2" ESD_FLIP-CHIP-BGA11_1P44X1P94_P050 284.582,213.335 r90 top
U19 "STMPS2141STR" MOS_SOT23-5L 246.177,204.8 r270 top
U20 "EMIF02-USB03F2" ESD_FLIP-CHIP-BGA11_1P44X1P94_P050 249.123,213.436 r270 top
U21 "TSV631AILT" SOT23-5 260.274,204.165 r90 top
X1 "Not Fitted (NX3225GD-8.00M)" CRY_NX3225GD_2P 260.553,176.809 r180 top
X2 "NX3215SA-32.768K" CRY_NX3215SA_2P 256.718,177.8 r0 top
X3 "NX3225GD-8.00M" CRY_NX3225GD_2P 283.159,187.02 r180 top

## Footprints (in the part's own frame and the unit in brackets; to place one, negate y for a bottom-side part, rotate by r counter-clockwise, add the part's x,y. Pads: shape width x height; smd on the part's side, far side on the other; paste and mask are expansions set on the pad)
0402_CAP_NPOL [mil] "Capacitor FootPrint 0402"
  rect 25x20 smd: 1(-25,0) 2(25,0)
  silkscreen extent -43,-15 43,16, body extent -39,-14 41,14, height 32
0402_RES [mil] "Resistor FootPrint 0402"
  rect 25x20 smd: 1(-25,0) 2(25,0)
  silkscreen extent -43,-15 43,16, body extent -38,-11 39,13, height 16
0603_CAP_NPOL [mm] "Capacitor FootPrint 0603"
  rect 0.8x1 smd: 1(-0.902,0) 2(0.902,0)
  silkscreen extent -1.41,-0.61 1.41,0.61, body extent -1.28,-0.46 1.26,0.48, height 0.82
0603_LED_Blue [mm] "Resistor Footprint 0603"
  rect 0.8x1 smd: A(0.902,0) K(-0.902,0)
  silkscreen extent -1.59,-0.61 1.41,0.61, body extent -1.26,-0.48 1.26,0.48, height 0.84
0603_LED_GREEN [mm] "Resistor Footprint 0603"
  rect 0.8x1 smd: A(0.902,0) K(-0.902,0)
  silkscreen extent -1.59,-0.61 1.41,0.61, body extent -1.26,-0.48 1.26,0.48, height 0.84
0603_LED_RED [mm] "Resistor Footprint 0603"
  rect 0.8x1 smd: A(0.902,0) K(-0.902,0)
  silkscreen extent -1.59,-0.61 1.41,0.61, body extent -1.26,-0.48 1.26,0.48, height 0.84
0603_LED_Yellow [mm] "Resistor Footprint 0603"
  rect 0.8x1 smd: A(0.902,0) K(-0.902,0)
  silkscreen extent -1.59,-0.61 1.41,0.61, body extent -1.26,-0.48 1.26,0.48, height 0.84
0603_RES [mm] "Resistor Footprint 0603"
  rect 0.8x1 smd: 1(-0.902,0) 2(0.902,0)
  silkscreen extent -1.41,-0.61 1.41,0.61, body extent -1.26,-0.48 1.26,0.48, height 0.4
0603L [mil]
  rect 30x30 smd: 1(27.5,0) 2(-27.5,0)
  silkscreen extent -50,-20 50,20
CON_SAMTEC_TSW-102-07-G-S [mm]
  rect 1.85x1.85 hole 1 mask+0.05: 1(-1.27,0)
  round 1.85 hole 1 mask+0.05: 2(1.27,0)
  silkscreen extent -2.58,-1.3 2.58,1.3, body extent -2.67,-1.3 2.58,1.3, height 8.38
CON_SAMTEC_TSW-104-07-G-S [mm]
  rect 1.85x1.85 hole 1 mask+0.05: 1(-3.81,0)
  round 1.85 hole 1 mask+0.05: 2(-1.27,0) 3(1.27,0) 4(3.81,0)
  silkscreen extent -5.12,-1.3 5.12,1.3, body extent -5.21,-1.37 5.18,1.37, height 8.38
CON_TAG-C_TC2050-IDC-NL [mm]
  round 0.9 smd paste-9 mask+0.05: 1(-2.54,-0.635)
  round 0.9 smd paste-0.9 mask+0.05: 2(-1.27,-0.635) 3(0,-0.635) 4(1.27,-0.635) 5(2.54,-0.635) 6(2.54,0.635) 7(1.27,0.635) 8(0,0.635) 9(-1.27,0.635) 10(-2.54,0.635)
  round 0 hole 1.1 unplated mask+0.05: 11(-3.81,0) 12(3.81,-1.015) 13(3.81,1.015)
  Multi-Layer keep-out circle w0.01: c-3.81,0 r0.75
  Multi-Layer keep-out circle w0.01: c3.81,1.015 r0.75
  Multi-Layer keep-out circle w0.01: c3.81,-1.015 r0.75
  silkscreen extent -6.22,-3.4 6.22,3.33
CON_USBMICROAB_MOLEX_47590-0001_H3 [mm]
  rect 0.4x1.35 smd mask+0.05: 1(1.3,4.125) 2(0.65,4.125) 3(0,4.125) 4(-0.65,4.125) 5(-1.3,4.125)
  oval 1.05x1.25 hole 0.65 slot 0.85 at 90 deg mask+0.05: 6(-2.225,4.45) 7(2.225,4.45)
  rrect50% 1.375x1.9 hole 0.6 slot 1.3 at 90 deg copper offset 0.188,0 mask+0.05: 8(-4.175,1.45)
  rrect50% 1.375x1.9 hole 0.6 slot 1.3 at 90 deg copper offset -0.188,0 mask+0.05: 9(4.175,1.45)
  rect 2.9x1.9 smd mask+0.05: 10(0,1.45)
  oval 0.85x2.425 hole 0.85 slot 2.425 at 90 deg unplated mask+0.1: 11(-2.375,0.8) 12(2.375,0.8)
  silkscreen extent -4.1,-1.3 4.1,4.3, body extent -4.32,-1.36 4.33,4.6, height 3
CON_USBMICROB_MOLEX_105017-0001_H2P90 [mm]
  rect 0.4x1.35 smd mask+0.05: 1(-1.3,4.15) 2(-0.65,4.15) 3(0,4.15) 4(0.65,4.15) 5(1.3,4.15)
  round 1.5 hole 0.9 mask+0.05: 6(-2.5,4.15) 7(2.5,4.15)
  oval 1.2x1.9 hole 0.6 slot 1.3 at 90 deg mask+0.05: 8(3.5,1.45) 9(-3.5,1.45)
  rect 1.5x1.9 smd mask+0.05: 10(-1,1.45) 11(1,1.45)
  Top Layer region: -3.5,2.4 -2.3,2.4 -2.3,0.5 -3.5,0.5 -3.5,2.4
  Top Layer region: 2.3,2.4 3.5,2.4 3.5,0.5 2.3,0.5 2.3,2.4
  silkscreen extent -4,-0.7 4,4.6, body extent -4.1,-1.15 4.1,4.66, height 2.9
CRY_NX3215SA_2P [mm]
  rect 1x1.8 smd mask+0.05: 1(-1.25,0) 2(1.25,0)
  body extent -1.65,-0.8 1.65,0.8, height 0.9
CRY_NX3225GD_2P [mm]
  rect 1.5x2.7 smd mask+0.05: 1(-0.95,0) 2(0.95,0)
  silkscreen extent -0.1,-1.3 0.1,1.3, body extent -1.65,-1.3 1.65,1.3, height 1
DIO_SOD323 [mm]
  rect 1.06x0.54 smd mask+0.05: 1(-1.07,0) 2(1.07,0)
  silkscreen extent -0.9,-0.72 0.9,0.72, body extent -1.3,-0.78 1.3,0.78, height 1.17
ESD_FLIP-CHIP-BGA11_1P44X1P94_P050 [mm]
  round 0.3 smd paste+0 mask+0.05: A2(0,0.75) A3(0.5,0.75) B1(-0.5,0.25) B2(0,0.25) B3(0.5,0.25) C1(-0.5,-0.25) C2(0,-0.25) C3(0.5,-0.25) D1(-0.5,-0.75) D2(0,-0.75) D3(0.5,-0.75)
  silkscreen extent -0.9,-1 0.75,1.15, body extent -0.7,-0.95 0.7,0.95, height 0.7
F-V50XC-1X06R-LF [mm] "Connector 6pts, 2.54mm  female smd"
  rect 1.02x2.7 smd: 1(6.35,-1.35) 3(1.27,-1.35) 5(-3.81,-1.35)
  rect 1.02x2.25 smd: 2(3.81,1.09) 4(-1.27,1.09) 6(-6.35,1.09)
  silkscreen extent -8.8,-3.32 8.8,2.17, body extent -8,-1.27 8,1.24, height 9.02
F-V50XC-1X08R-LF#1 [mm] "Connector 8pts, 2.54mm  female smd"
  rect 1.02x2.7 smd: 1(8.89,-1.35) 2(6.35,1.35) 3(3.81,-1.35) 4(1.27,1.35) 5(-1.27,-1.35) 7(-6.35,-1.35)
  rect 1.02x2.25 smd: 6(-3.81,1.09) 8(-8.89,1.09)
  silkscreen extent -10.6,-3.32 10.6,2.15, body extent -10.54,-1.24 10.49,1.27, height 9.02
F-V50XC-1X08R-LF#2 [mm] "Connector 8pts, 2.54mm  female smd"
  rect 1.02x2.7 smd: 1(8.89,-1.35) 3(3.81,-1.35) 4(1.27,1.35) 5(-1.27,-1.35) 6(-3.81,1.35) 7(-6.35,-1.35) 8(-8.89,1.35)
  rect 1.02x2.5 smd: 2(6.35,1.15)
  silkscreen extent -10.6,-3.32 10.6,2.15, body extent -10.54,-1.24 10.49,1.27, height 9.02
F-V50XC-1X10R-LF [mm] "Connector 10pts, 2.54mm  female smd"
  rect 1.02x2.7 smd: 1(11.43,-1.35) 2(8.89,1.35) 3(6.35,-1.35) 4(3.81,1.35) 5(1.27,-1.35) 6(-1.27,1.35) 7(-3.81,-1.35) 8(-6.35,1.35) 9(-8.89,-1.35) 10(-11.43,1.35)
  silkscreen extent -13,-3.32 13.2,2.15, body extent -13.08,-1.27 13.13,1.24, height 9.02
"HCLGA-4LD 3x4x1" [mm] "HCLGA-4LD 3x4x1mm (MP34DT01_Microphone MEMS)"
  rect 0.4x0.95 smd mask+0.02: 1(-0.425,0.675) 2(-0.425,-0.675) 3(0.425,-0.675) 4(0.425,0.675)
  rect 0.35x2.3 smd mask+0.02: 5(-1.225,0) 5(1.225,0)
  rect 1.3x0.35 smd mask+0.02: 5(0,1.725) 5(0,-1.725)
  silkscreen extent -1.91,-2 1.5,2.44, body extent -1.5,-2.01 1.5,2.01, height 1.01
"Header F 2x6x2.54 TH H PMOD" [mm] "2x6x2.54 Header TH H Female PMOD Warning Specific Pinout"
  rect 1.8x1.8 hole 1: 1(0,0)
  round 1.8 hole 1: 2(2.54,0) 3(5.08,0) 4(7.62,0) 5(10.16,0) 6(12.7,0) 7(0,2.54) 8(2.54,2.54) 9(5.08,2.54) 10(7.62,2.54) 11(10.16,2.54) 12(12.7,2.54)
  silkscreen extent -1.47,-1.43 14.05,12.7, body extent -1.42,-0.32 14.07,12.71, height 5.04
"Header M 2x5x2.54 TH V" [mm] "2x5x2.54 Header TH V Male"
  rect 1.8x1.8 hole 1: 1(0,0)
  round 1.8 hole 1: 2(0,2.54) 3(2.54,0) 4(2.54,2.54) 5(5.08,0) 6(5.08,2.54) 7(7.62,0) 8(7.62,2.54) 9(10.16,0) 10(10.16,2.54)
  silkscreen extent -1.47,-1.43 11.56,3.97, body extent -1.3,-1.24 11.4,3.84, height 8.5
HLGA6L-2x2x0.9 [mm] "HLGA6L 2x2x0.9mm pitch1mm"
  rect 0.4x0.35 smd mask+0.05: 1(-0.675,0.5) 2(-0.675,-0.5) 4(0.675,-0.5) 5(0.675,0.5)
  rect 0.35x0.4 smd mask+0.05: 3(0,-0.675) 6(0,0.675)
  silkscreen extent -1.45,-1.02 1.02,1.46, body extent -1.02,-1.02 1.02,1.02, height 1
HLGA10L-2X2X0.76 [mm] "HLGA-10L 2x2x0.76mm pitch 0.5mm"
  oct 0.275x0.25 smd paste+0 mask+0.05: 1(-0.763,0.25)
  rect 0.275x0.25 smd paste+0 mask+0.05: 2(-0.763,-0.25) 6(0.763,-0.25) 7(0.763,0.25)
  rect 0.25x0.275 smd paste+0 mask+0.05: 3(-0.5,-0.763) 4(0,-0.763) 5(0.5,-0.763) 8(0.5,0.763) 9(0,0.763) 10(-0.5,0.763)
  silkscreen extent -1.5,-1 1,1, body extent -1.02,-1.02 1.02,1.02, height 0.77
ICC_LQFP48_7X7_P050 [mm]
  rect 0.3x1.2 smd mask+0.05: 1(-2.75,-4.25) 2(-2.25,-4.25) 3(-1.75,-4.25) 4(-1.25,-4.25) 5(-0.75,-4.25) 6(-0.25,-4.25) 7(0.25,-4.25) 8(0.75,-4.25) 9(1.25,-4.25) 10(1.75,-4.25) 11(2.25,-4.25) 12(2.75,-4.25) 25(2.75,4.25) 26(2.25,4.25) 27(1.75,4.25) 28(1.25,4.25) 29(0.75,4.25) 30(0.25,4.25) 31(-0.25,4.25) 32(-0.75,4.25) 33(-1.25,4.25) 34(-1.75,4.25) 35(-2.25,4.25) 36(-2.75,4.25)
  rect 1.2x0.3 smd mask+0.05: 13(4.25,-2.75) 14(4.25,-2.25) 15(4.25,-1.75) 16(4.25,-1.25) 17(4.25,-0.75) 18(4.25,-0.25) 19(4.25,0.25) 20(4.25,0.75) 21(4.25,1.25) 22(4.25,1.75) 23(4.25,2.25) 24(4.25,2.75) 37(-4.25,2.75) 38(-4.25,2.25) 39(-4.25,1.75) 40(-4.25,1.25) 41(-4.25,0.75) 42(-4.25,0.25) 43(-4.25,-0.25) 44(-4.25,-0.75) 45(-4.25,-1.25) 46(-4.25,-1.75) 47(-4.25,-2.25) 48(-4.25,-2.75)
  silkscreen extent -3.52,-3.52 3.52,3.52, body extent -4.5,-4.5 4.5,4.5, height 1.6
ICC_SO8_5X4_P127 [mm]
  rect 0.7x1.75 smd mask+0.05: 1(-1.905,-2.375) 2(-0.635,-2.375) 3(0.635,-2.375) 4(1.905,-2.375) 5(1.905,2.375) 6(0.635,2.375) 7(-0.635,2.375) 8(-1.905,2.375)
  silkscreen extent -2.58,-2 2.58,2, body extent -2.57,-3 2.57,3, height 1.75
ISM43362-M3G-L44 [mm] "ISM43362-M3G-L44 Module Wifi 802.11 bgn"
  rect 0.84x0.84 smd: 1(8.742,6.88) 2(7.285,6.88) 3(5.828,6.88) 4(4.371,6.88) 5(2.914,6.88) 6(1.457,6.88) 7(0,6.88) 8(-1.457,6.88) 9(-2.914,6.88) 10(-4.371,6.88) 11(-5.828,6.88) 12(-7.285,6.88) 13(-8.742,6.88) 14(-9.942,5.68) 15(-9.942,4.26) 16(-9.942,2.84) 17(-9.942,1.42) 18(-9.942,0) 19(-9.942,-1.42) 20(-9.942,-2.84) 21(-9.942,-4.26) 22(-9.942,-5.68) 23(-8.742,-6.88) 24(-7.285,-6.88) 25(-5.828,-6.88) 26(-4.371,-6.88) 27(-2.914,-6.88) 28(-1.457,-6.88) 29(0,-6.88) 30(1.457,-6.88) 31(2.914,-6.88) 32(4.371,-6.88) 33(5.828,-6.88) 34(7.285,-6.88) 35(8.742,-6.88) 36(9.942,-5.68) 37(9.942,-4.26) 38(9.942,-2.84) 39(9.942,-1.42) 40(9.942,0) 41(9.942,1.42) 42(9.942,2.84) 43(9.942,4.26) 44(9.942,5.68)
  silkscreen extent -10.65,-9.63 19.64,9.73, body extent -10.64,-7.32 19.66,7.32, height 2.7
LED_BI-GR_HSMF-A201-A00J1 [mm]
  rect 1.1x1.5 smd mask+0.05: 1(-0.75,-1.5) 2(-0.75,1.5) 3(0.75,1.5) 4(0.75,-1.5)
  silkscreen extent -1.65,-1.85 1.65,1.85, body extent -1.5,-1.85 1.5,1.85, height 2.1
LGA12-optical [mm] "VL53L0X : World smallest Time-of-Flight ranging and gesture detection sensor"
  rect 0.5x0.5 smd: 1(1.6,-0.8) 2(0.8,-0.8) 3(0,-0.8) 4(-0.8,-0.8) 5(-1.6,-0.8) 6(-1.6,0) 7(-1.6,0.8) 8(-0.8,0.8) 9(0,0.8) 10(0.8,0.8) 11(1.6,0.8) 12(1.6,0)
  rect 0.08x0.25 smd: 1(1.89,-0.675)
  silkscreen extent -2.2,-1.65 2.67,1.2, body extent -2.18,-1.22 2.21,1.19, height 1.01
LGA14L-2.5X3X0.86p0.5 [mm] "LGA14 2.5x3x0.86mm pitch0.5mm"
  rect 0.75x0.3 smd mask+0.05: 1(-1.33,0.75) 2(-1.33,0.25) 3(-1.33,-0.25) 4(-1.33,-0.75) 8(1.33,-0.75) 9(1.33,-0.25) 10(1.33,0.25) 11(1.33,0.75)
  rect 0.3x0.75 smd mask+0.05: 5(-0.5,-1.1) 6(0,-1.1) 7(0.5,-1.1) 12(0.5,1.1) 13(0,1.1) 14(-0.5,1.1)
  silkscreen extent -2.16,-1.25 1.52,1.8, body extent -1.52,-1.27 1.52,1.27, height 0.9
"LOGO CE" [mm]
  silkscreen extent -3.27,-3.31 4.33,3.3
LOGO_ST_Size3 [mm]
  silkscreen extent -4.5,-2.36 4.7,2.57
"LQFP100 14x14x1.6" [mm] "LQFP100 14x14mm low profile 1.6mm"
  rect 1.2x0.3 smd: 1(-7.75,6) 2(-7.75,5.5) 3(-7.75,5) 4(-7.75,4.5) 5(-7.75,4) 6(-7.75,3.5) 7(-7.75,3) 8(-7.75,2.5) 9(-7.75,2) 10(-7.75,1.5) 11(-7.75,1) 12(-7.75,0.5) 13(-7.75,0) 14(-7.75,-0.5) 15(-7.75,-1) 16(-7.75,-1.5) 17(-7.75,-2) 18(-7.75,-2.5) 19(-7.75,-3) 20(-7.75,-3.5) 21(-7.75,-4) 22(-7.75,-4.5) 23(-7.75,-5) 24(-7.75,-5.5) 25(-7.75,-6) 51(7.75,-6) 52(7.75,-5.5) 53(7.75,-5) 54(7.75,-4.5) 55(7.75,-4) 56(7.75,-3.5) 57(7.75,-3) 58(7.75,-2.5) 59(7.75,-2) 60(7.75,-1.5) 61(7.75,-1) 62(7.75,-0.5) 63(7.75,0) 64(7.75,0.5) 65(7.75,1) 66(7.75,1.5) 67(7.75,2) 68(7.75,2.5) 69(7.75,3) 70(7.75,3.5) 71(7.75,4) 72(7.75,4.5) 73(7.75,5) 74(7.75,5.5) 75(7.75,6)
  rect 0.3x1.2 smd: 26(-6,-7.75) 27(-5.5,-7.75) 28(-5,-7.75) 29(-4.5,-7.75) 30(-4,-7.75) 31(-3.5,-7.75) 32(-3,-7.75) 33(-2.5,-7.75) 34(-2,-7.75) 35(-1.5,-7.75) 36(-1,-7.75) 37(-0.5,-7.75) 38(0,-7.75) 39(0.5,-7.75) 40(1,-7.75) 41(1.5,-7.75) 42(2,-7.75) 43(2.5,-7.75) 44(3,-7.75) 45(3.5,-7.75) 46(4,-7.75) 47(4.5,-7.75) 48(5,-7.75) 49(5.5,-7.75) 50(6,-7.75) 76(6,7.75) 77(5.5,7.75) 78(5,7.75) 79(4.5,7.75) 80(4,7.75) 81(3.5,7.75) 82(3,7.75) 83(2.5,7.75) 84(2,7.75) 85(1.5,7.75) 86(1,7.75) 87(0.5,7.75) 88(0,7.75) 89(-0.5,7.75) 90(-1,7.75) 91(-1.5,7.75) 92(-2,7.75) 93(-2.5,7.75) 94(-3,7.75) 95(-3.5,7.75) 96(-4,7.75) 97(-4.5,7.75) 98(-5,7.75) 99(-5.5,7.75) 100(-6,7.75)
  silkscreen extent -7.87,-6.3 6.3,6.82, body extent -7,-7 7,7, height 1.65
MOS_SOT23-5L [mm]
  rect 0.6x1.3 smd mask+0.05: 1(-0.95,-1.1) 2(0,-1.1) 3(0.95,-1.1) 4(0.95,1.1) 5(-0.95,1.1)
  silkscreen extent -1.6,-0.95 1.6,0.97, body extent -1.52,-1.25 1.52,1.25, height 1.45
PTB [mm]
  rect 2x1 smd: 1(0,0)
  silkscreen extent -1.1,-0.6 1.1,0.6
REG_SOT23-5L [mm]
  rect 0.6x1.3 smd mask+0.05: 1(-0.95,-1.1) 2(0,-1.1) 3(0.95,-1.1) 4(0.95,1.1) 5(-0.95,1.1)
  silkscreen extent -1.6,-0.95 1.6,0.97, body extent -1.52,-1.25 1.52,1.25, height 1.1
REG_SOT223-TAB [mm]
  rect 1.5x1.65 smd mask+0.05: 1(-2.3,-3.175) 2(0,-3.175) 3(2.3,-3.175)
  rect 3.5x1.65 smd mask+0.05: 4(0,3.175)
  silkscreen extent -3.35,-2.15 3.35,2.12, body extent -3.35,-3.48 3.35,3.48, height 1.8
SB [mil]
  round 10 smd paste-10: 1(-19.68,0)
  round 10 smd paste-10.08: 2(23.62,0)
  Top Layer region: -5.91,19.68 13.78,0 -5.91,-19.69 47.24,-19.69 47.24,19.68
  Top Layer region: -47.24,-19.69 -47.24,19.68 -15.75,19.68 3.94,0 -15.75,-19.69
  silkscreen extent -50,-23 50,23
SOP8 [mm] "SOP, 8-Leads, Body 5.0x4.0mm (max), Pitch 1.27mm, IPC Medium Density"
  rect 2.2x0.6 smd: 1(-2.425,1.905)
  oval 2.2x0.6 smd: 2(-2.425,0.635) 3(-2.425,-0.635) 4(-2.425,-1.905) 5(2.425,-1.905) 6(2.425,-0.635) 7(2.425,0.635) 8(2.425,1.905)
  silkscreen extent -2.64,-2.54 2.03,3.02, body extent -2.97,-2.45 3.17,2.44, height 1.73
SOP8L [mm] "SOP, 8-Leads, Body 5.0x4.0mm (max), Pitch 1.27mm, IPC Medium Density"
  rect 2.2x0.6 smd: 1(-3.32,1.905)
  oval 2.2x0.6 smd: 2(-3.32,0.635) 3(-3.32,-0.635) 4(-3.32,-1.905) 5(3.32,-1.905) 6(3.32,-0.635) 7(3.32,0.635) 8(3.32,1.905)
  silkscreen extent -2.64,-2.54 2.03,3.02, body extent -2.97,-2.45 3.17,2.44, height 1.73
SOT23-3 [mm]
  rect 0.9x0.95 smd: 1(-0.95,-2.35) 2(0.95,-2.35) 3(0,0)
  silkscreen extent -1.9,-3.35 1.3,0, body extent -1.27,-1.8 1.32,-0.51, height 1.05
SOT23-5 [mil]
  rect 50x20 smd: 1(-50,37.5) 2(-50,0.5) 3(-50,-37.5) 4(50,-37.5) 5(50,37.5)
  silkscreen extent -104,-7 55,77, body extent -32,-57 32,57, height 47
SOT223_SC73 [mil]
  rect 39x59 smd: 1(-90,-124) 2(0,-124) 3(90,-124)
  rect 129x59 smd: 2(0,124)
  silkscreen extent -140,-71 138,70, body extent -128,-136 128,138, height 65
"Spacer+Nut M3" [mm] "Spacer+Nut M3 Mechanical Only"
  body extent -3.17,-2.75 3.18,2.75, height 5.5
SPBTLE-RF [mm]
  rect 1.6x1 smd: 1(0,0) 2(0,-1.27) 3(0,-2.54) 4(0,-3.81) 5(0,-5.08) 7(13.5,-5.08) 8(13.5,-3.81) 9(13.5,-2.54) 10(13.5,-1.27) 11(13.5,0)
  rect 1x1.6 smd: 6(4,-6.08)
  silkscreen extent -0.69,-5.88 13.5,5.72, body extent -0.03,-5.89 13.51,5.72, height 2.1
SPSGRF [mm]
  rect 1.6x1 smd: 1(0,0) 2(0,-1.27) 3(0,-2.54) 4(0,-3.81) 5(0,-5.08) 7(13.5,-5.08) 8(13.5,-3.81) 9(13.5,-2.54) 10(13.5,-1.27) 11(13.5,0)
  rect 1x1.6 smd: 6(4,-6.08)
  silkscreen extent -0.64,-5.88 13.5,5.72, body extent 0.03,-5.89 13.51,5.72, height 2.1
"SWI_WEALTHMETAL_TD-0341_4P - BACK" [mm] "SMD Push Button with Back Plastic"
  rect 1.52x2.16 smd mask+0.05: 1(-2.25,-4.75) 1(-2.25,4.75) 2(2.25,-4.75) 2(2.25,4.75)
  silkscreen extent -3,-3.5 3,3.5, body extent -3,-5 3,5, height 6
"SWI_WEALTHMETAL_TD-0341_4P - BLUE" [mm] "SMD Push Button with Back Plastic"
  rect 1.52x2.16 smd mask+0.05: 1(-2.25,-4.75) 1(-2.25,4.75) 2(2.25,-4.75) 2(2.25,4.75)
  silkscreen extent -3,-3.5 3,3.5, body extent -3,-5 3,5, height 6
SYMBOL_ESD [mm]
  silkscreen extent -3.46,-2.52 3.25,3.62
SYMBOL_RoHS [mm]
  silkscreen extent 0,0 9.5,6
VFLGA12-2x2x1 [mm] "LGA12 2x2x1mm"
  rect 0.3x0.3 smd mask+0.05: 1(-0.75,0.75) 2(-0.75,0.25) 3(-0.75,-0.25) 4(-0.75,-0.75) 5(-0.25,-0.75) 6(0.25,-0.75) 7(0.75,-0.75) 8(0.75,-0.25) 9(0.75,0.25) 10(0.75,0.75) 11(0.25,0.75) 12(-0.25,0.75)
  silkscreen extent -1.47,-1.02 1.02,1.45, body extent -1.02,-1.02 1.02,1.02, height 1.1

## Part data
B1 B2: library part SW-PB_2, "Push-button SMD"
C1 C2 C3 C4 C5 C6 C7 C8 C9 C10 C11 C12 C13 C14 C15 C16 C17 C18 C19 C20 C21 C22 C23 C24 C25 C26 C27 C28 C29 C30 C31 C32 C33 C34 C35 C36 C37 C38 C39 C40 C41 C42 C43 C44 C45 C46 C47 C48 C49 C50 C51 C52 C53 C54 C55 C56 C57 C58 C59 C60 C61 C62 C63 C64 C65 C66 C67 C68 C69 C70 C71 C72 C73 C74 C75 C76: library part CAP_NPOL, "Capacitor_not polarized"
CN1: "Header, 10-Pin, SMD, Single row,female"
CN2 CN3: "Header, 8-Pin, SMD, Single row,female"
CN4: "Header, 6-Pin, SMD, Single row,female"
CN5: library part Tag-10-C, "Tag_Connector Header, 10-Pin, Dual row No legs"
CN6: library part "Header 2 pins", "Header 2 pins"
CN7: "USB-MICRO-B, 1050170001, SMT, MOLEX"
CN8: library part "Header 4", "Header, 4-Pin"
CN9: "USB-MICRO-AB, 47590-0001, SMT, MOLEX"
CN10: "PMOD Connector Warning Specific Pinout"
JP5 JP6 JP7 JP8: library part TSW-102-07-x-S, "Connector jumper 1 position"
L1 L2: library part Inductor, "Inductor"
LD1 LD2 LD3 LD4 LD5 LD7 LD8 LD9: "Light-Emitting Diode"
LD6: "Bicolor Led"
M1: library part SPBTLE-RF, "SPBTLE-RF"
M2: "ISM43362-M3G-L44 Wifi Module 802.11 bgn"
M3: "SPSGRF-915or SPSGRF-868"
Q1 Q2: "BSR14 NPN switching transistor SOT23 (Marking U8)"
R1 R2 R3 R4 R5 R6 R7 R8 R9 R10 R11 R12 R13 R14 R15 R16 R18 R19 R20 R21 R22 R23 R24 R25 R26 R27 R28 R29 R30 R31 R32 R33 R34 R35 R36 R38 R39 R40 R41 R42 R43 R44 R45 R46 R47 R48 R49 R50 R51 R52 R53 R54 R55 R56 R57 R58 R59 R61 R62 R64 R65 R66 R67: library part RES, "Resistor"
SB1 SB2 SB3 SB4 SB5 SB6 SB7 SB8 SB9 SB10 SB11 SB12 SB13 SB14 SB15 SB16 SB17 SB18 SB19 SB20 SB21: library part Strap2, "Solder Jumper"
TP1 TP2 TP3 TP4 TP5 TP6: "Point de test"
U2 U10: library part MP34DT01, "MEMS audio microphone"
U3: "Accelero + Gyro MEMS (6 Axis)"
U4: "Proximity sensor MEMS"
U5 U7: "IC,Sensor"
U6: "Humidity + Temp MEMS"
U8: "M24SR64-Y  64K_EEPROM NFC/RFID"
U11: "MX25R6435F Serial Flash Memory 64M"
U12: "LT1963EST-3.3 LDO Low Noise 1.5A fast Transient Response"
U13: "IC REG LDO 5V 0.8A SOT223"
U14: "LOW DROP FIXED AND ADJUSTABLE POSITIVE VOLTAGE REGULATORS (3.3 Volts)"
U15: "Medium-density performance line ARM-based 32-bit MCU with 128KB Flash"
U16: "Ultra low drop-low noise BiCMOS voltage, regulators low ESR capacitors compatible"
U17: "1.2 A current limited high-side power switch with thermal shutdown"
U18 U20: "2-line IPAD, EMI filter including ESD protection"
U19: "Enhanced single channel power switches"
U21: "TSV631AILT  Rail-to-rail input/output, 60 µA, 880 kHz, 5 V CMOS  operational amplifiers"
X1 X3: library part XTAL_8M_NX3225GD, "Crystal 8Mhz, 8pF, -+50PPM, SMD"
X2: library part XTAL_32K_NX3215SA, "Crystal 32.768kHz, 6pF, -+20PPM, R=50K, SMD"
